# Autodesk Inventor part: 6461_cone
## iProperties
Author: Ole Germer
Shininess: 64.0
Angle Display Precision: 2
Document Length Units: 11272
Document Angle Units: 11286
Document Time Units: 11279
Document Mass Units: 11290
Document Length Units Precision: 3
Document Angle Units Precision: 2
Compacted: True
PropertySet Name: _Private Model Information
Created: 2002-10
Part Number: 6461_cone
Material: Stainless Steel, 440C
Document SubType Name: Modeling
Designer: Ole Germer
Control State: 0
Master: False
Checked Out: False
PropertySet Name: Design Tracking Control
Density: 0.0
Volumn: 0.0
Area: 0.0
PropertySet Name: Model Information
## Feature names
1. Revolution1
